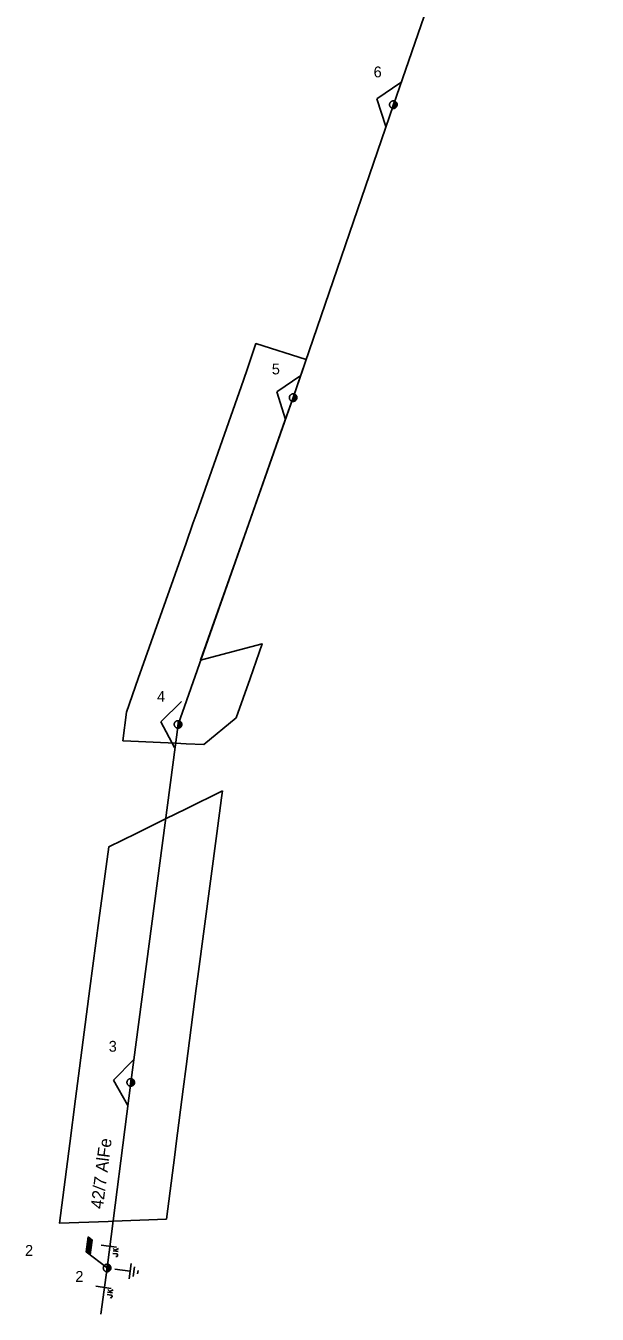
# Model space of a CAD drawing. Extents: x -536397 to -535454, y -1201642 to -1200953.
# Drawn here: x -535913.3 to -535821.2, y -1201640.1 to -1201432.2 of the extents above; entities that cross this region are included whole.
import ezdxf

# ---------------------------------------------------------------- set-up
doc = ezdxf.new("R2010")
doc.units = 0
for name, color, linetype in [('DOPLŇ_POPISY', 7, 'Continuous'), ('ELE_EON_POPIS', 7, 'Continuous'), ('Implicitní', 7, 'Continuous'), ('KN_HRAN_POHYBLIVÁ', 7, 'Continuous'), ('KONEC_VEDENÍ', 7, 'Continuous'), ('PB_NN', 7, 'Continuous'), ('PK_HRAN_SPORNÁ', 7, 'Continuous'), ('PLG_EXPORT_GPE', 7, 'Continuous'), ('PODZEM_NN_POPIS', 7, 'Continuous'), ('RÁMEČEK', 7, 'Continuous'), ('TECH_OCHR_PÁSMO_HRAN', 7, 'Continuous')]:
    doc.layers.add(name, color=color, linetype=linetype)

# ---------------------------------------------------------------- blocks, each defined once
blk = doc.blocks.new('VN840')
at = {"layer": 'RÁMEČEK'}
for points in [[(-0.01, 1.41), (-0.01, -1.09)], [(-1.51, -1.24), (-1.51, -1.15)], [(-1.48, -1.35), (-1.51, -1.24)], [(-1.33, -1.42), (-1.48, -1.35)], [(-1.27, -1.42), (-1.33, -1.42)], [(-1.13, -1.35), (-1.27, -1.42)], [(-1.09, -1.24), (-1.13, -1.35)], [(-1.09, -0.59), (-1.09, -1.24)], [(-0.68, -0.59), (-0.68, -1.42)], [(-0.68, -1.11), (-0.27, -0.59)], [(-0.54, -0.94), (-0.2, -1.42)]]:
    blk.add_lwpolyline(points, dxfattribs=at)
blk = doc.blocks.new('VN860')
at = {"layer": 'RÁMEČEK'}
for points in [[(-3.74, 0), (0.01, 2.82)], [(0.01, 2.82), (3.76, 0)]]:
    blk.add_lwpolyline(points, dxfattribs=at)
blk = doc.blocks.new('VN440')
at = {"layer": 'ELE_EON_POPIS'}
for points in [[(1.22, 0), (1.21, 0.13), (1.19, 0.25), (1.16, 0.38), (1.11, 0.5), (1.05, 0.61), (0.98, 0.72), (0.9, 0.82), (0.81, 0.91), (0.71, 0.99), (0.6, 1.06), (0.49, 1.12), (0.37, 1.16), (0.25, 1.2), (0.12, 1.22), (-0.01, 1.22), (-0.14, 1.22), (-0.26, 1.2), (-0.39, 1.16), (-0.51, 1.12), (-0.62, 1.06), (-0.73, 0.99), (-0.83, 0.91), (-0.92, 0.82), (-1, 0.72), (-1.07, 0.61), (-1.13, 0.5), (-1.18, 0.38), (-1.21, 0.25), (-1.23, 0.13), (-1.24, 0), (-1.23, -0.13), (-1.21, -0.26), (-1.18, -0.38), (-1.13, -0.5), (-1.07, -0.62), (-1, -0.73), (-0.92, -0.83), (-0.83, -0.92), (-0.73, -1), (-0.62, -1.07), (-0.51, -1.13), (-0.39, -1.17), (-0.26, -1.2), (-0.14, -1.23), (-0.01, -1.23), (0.12, -1.23), (0.25, -1.2), (0.37, -1.17), (0.49, -1.13), (0.6, -1.07), (0.71, -1), (0.81, -0.92), (0.9, -0.83), (0.98, -0.73), (1.05, -0.62), (1.11, -0.5), (1.16, -0.38), (1.19, -0.26), (1.21, -0.13), (1.22, 0)], [(-1.24, 0), (1.22, 0)], [(-1.18, -0.34), (1.1, -0.34)], [(-1.01, -0.63), (0.97, -0.63)], [(-0.74, -0.92), (0.68, -0.92)]]:
    blk.add_lwpolyline(points, dxfattribs=at)
blk = doc.blocks.new('VN810')
at = {"layer": 'PLG_EXPORT_GPE'}
for points in [[(0, -1.25), (0, -3.75)], [(1.25, -3.75), (-1.25, -3.75)], [(0.77, -4.37), (-0.8, -4.37)], [(0, -5), (-0.25, -5)], [(0.27, -5), (0, -5)]]:
    blk.add_lwpolyline(points, dxfattribs=at)
blk = doc.blocks.new('VN001')
at = {"layer": 'Implicitní'}
for p, q in [((1.73, 3.03), (4.14, 3.03)), ((1.76, 3.08), (4.17, 3.08)), ((1.79, 3.13), (4.2, 3.13)), ((1.82, 3.18), (4.23, 3.18)), ((1.85, 3.23), (4.26, 3.23)), ((1.87, 3.28), (4.29, 3.28)), ((1.9, 3.33), (4.32, 3.33)), ((1.93, 3.38), (4.35, 3.38)), ((1.96, 3.43), (4.37, 3.43)), ((1.99, 3.48), (4.4, 3.48)), ((2.02, 3.53), (4.43, 3.53)), ((2.05, 3.58), (4.46, 3.58)), ((2.07, 3.63), (4.49, 3.63)), ((2.1, 3.68), (4.52, 3.68)), ((2.13, 3.73), (2.54, 3.73))]:
    blk.add_line(p, q, dxfattribs=at)
blk.add_lwpolyline([(2.13, 3.73), (0, 0)], dxfattribs=at)
blk.add_lwpolyline([(4.55, 3.73), (2.13, 3.73), (1.7, 2.98), (4.12, 2.99)], close=True, dxfattribs=at)

msp = doc.modelspace()

# ---------------------------------------------------------------- linework, layer by layer
at = {"layer": 'PK_HRAN_SPORNÁ'}
for points in [[(-535897.71, -1201547.56), (-535897.1, -1201542.93), (-535895.19, -1201537.5), (-535887.5, -1201515.66), (-535886.39, -1201512.5), (-535885.78, -1201510.78), (-535878.26, -1201489.41), (-535877.61, -1201487.5), (-535876.23, -1201483.48), (-535868.13, -1201486.05), (-535868.63, -1201487.5), (-535870.23, -1201492.2), (-535871.88, -1201496.88), (-535877.38, -1201512.5), (-535885.15, -1201534.57), (-535884.36, -1201534.36), (-535875.21, -1201531.94), (-535877.17, -1201537.5), (-535879.4, -1201543.84), (-535884.62, -1201548.17), (-535887.5, -1201548.04), (-535889.19, -1201547.96), (-535897.57, -1201547.57)], [(-535881.63, -1201555.62), (-535881.78, -1201556.78), (-535882.54, -1201562.5), (-535885.58, -1201585.58), (-535885.84, -1201587.5), (-535887.5, -1201600.12), (-535887.98, -1201603.76), (-535889.09, -1201612.5), (-535889.33, -1201614.33), (-535890.65, -1201624.7), (-535899.26, -1201625.04), (-535900.07, -1201625.07), (-535907.87, -1201625.37), (-535906.23, -1201612.5), (-535905.32, -1201605.32), (-535904.84, -1201601.58), (-535902.98, -1201587.5), (-535901.53, -1201576.53), (-535899.97, -1201564.68), (-535895.56, -1201562.5), (-535890.8, -1201560.15), (-535887.5, -1201558.52)]]:
    msp.add_lwpolyline(points, close=True, dxfattribs=at)
at = {"layer": 'PODZEM_NN_POPIS'}
for points in [[(-535900.22, -1201632.59), (-535896.41, -1201602.67), (-535888.79, -1201544.92), (-535870.23, -1201492.2), (-535854.08, -1201444.95), (-535839.27, -1201402.16), (-535821.22, -1201351.74)], [(-535901.25, -1201640.05), (-535900.22, -1201632.59)]]:
    msp.add_lwpolyline(points, dxfattribs=at)

# ---------------------------------------------------------------- block references
at = {"layer": 'DOPLŇ_POPISY', "xscale": 0.5}
for p, yscale, rotation in [((-535854.08, -1201444.95), 0.5, 71.12953331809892), ((-535870.23, -1201492.2), 0.5, 70.60537496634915), ((-535888.79, -1201544.92), 0.5000000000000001, 82.48322216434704), ((-535896.41, -1201602.67), 0.5, 82.74278051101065), ((-535900.22, -1201632.59), 0.49999999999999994, 82.16094441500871)]:
    msp.add_blockref('VN440', p, dxfattribs=dict(at, yscale=yscale, rotation=rotation))
at = {"layer": 'KN_HRAN_POHYBLIVÁ'}
for name, p, rotation in [('VN860', (-535854.08, -1201444.95), 71.12941941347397), ('VN860', (-535870.23, -1201492.2), 70.605499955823), ('VN860', (-535888.79, -1201544.92), 81.3135889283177), ('VN860', (-535896.41, -1201602.67), 82.7432222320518), ('VN840', (-535899.77, -1201629.09), 82.7430361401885), ('VN840', (-535900.65, -1201635.72), 82.16127775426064)]:
    msp.add_blockref(name, p, dxfattribs=dict(at, rotation=rotation))
at = {"layer": 'RÁMEČEK', "rotation": 82.16137222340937}
msp.add_blockref('VN810', (-535900.22, -1201632.59), dxfattribs=at)
at = {"layer": 'TECH_OCHR_PÁSMO_HRAN', "rotation": 82.16037223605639}
msp.add_blockref('VN001', (-535900.22, -1201632.59), dxfattribs=at)

# ---------------------------------------------------------------- texts
at = {"layer": 'KONEC_VEDENÍ'}
msp.add_text('2', height=1.75, dxfattribs=at).set_placement((-535913.45, -1201630.64))
at = {"layer": 'PB_NN'}
msp.add_text('42/7 AlFe', height=2, rotation=82.743, dxfattribs=at).set_placement((-535900.91, -1201623.15))
at = {"layer": 'PLG_EXPORT_GPE'}
for s, p in [('6', (-535857.26, -1201440.54)), ('5', (-535873.67, -1201488.46)), ('4', (-535892.17, -1201541.27)), ('3', (-535899.96, -1201597.71)), ('2', (-535905.34, -1201634.83))]:
    msp.add_text(s, height=1.75, dxfattribs=at).set_placement(p)

doc.saveas('drawing.dxf')
